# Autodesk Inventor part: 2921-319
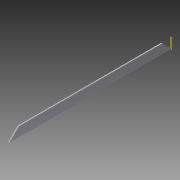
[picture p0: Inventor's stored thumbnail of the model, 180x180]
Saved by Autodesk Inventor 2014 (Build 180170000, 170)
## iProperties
Company: NHTSA/VRTC
Created: 2011-11
Part Number: 2921-319
Material: Steel
Document SubType Name: Modeling
Designer: Mike Vanvoorhis
Density: 7.85 g/cm^3
Project: CHILD SIDE IMPACT SLED
Description: BENCH CROSS BRACE PLATE
Mass: 2103.52 g
Surface Area: 952.081 cm^2
Volume: 267.964 cm^3
Stock Number: PL 6.4 (1/4") x 50.8 (2") x 875.0 (34 7/16")
Appearance: Steel
DESIGN DATE: 2012-11-05
Author: Dave Walker
Title: Bench Cross Brace Plate
Subject: Child Side Impact Sled
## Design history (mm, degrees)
node "Sketch1"
node "2921-2051"
workplane "Work Plane4"
node "2921-205"
node "Base1"
